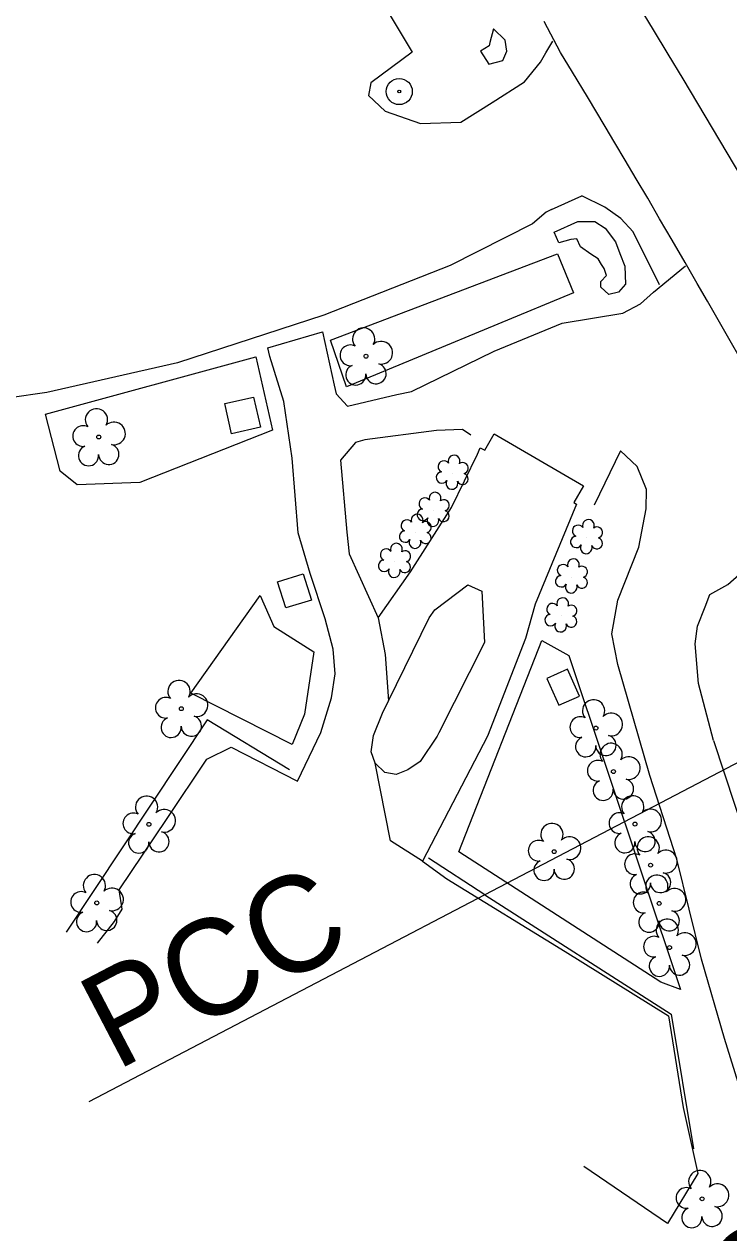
# Model space of a CAD drawing. Extents: x 471894 to 476235, y 503501 to 507878.
# Drawn here: x 474140.1 to 474257.8, y 505265.7 to 505467.5 of the extents above; entities that cross this region are included whole.
import ezdxf

# ---------------------------------------------------------------- set-up
doc = ezdxf.new("R2010")
doc.units = 0
for name, color, linetype in [('Exist Horizontal Alignment', 7, 'Continuous'), ('Exist Other Culture Area Outline', 7, 'Continuous'), ('Exist Other Culture Fence Line', 7, 'Continuous'), ('Exist Other Culture Sign Post CELL', 7, 'Continuous'), ('Exist Roads EOP', 7, 'Continuous'), ('Exist Roads EOP Other', 7, 'Continuous'), ('Exist Roads Soil', 7, 'Continuous'), ('Exist Vegetation Hedge Row', 7, 'Continuous'), ('Exist Vegetation Shrub CELL', 7, 'Continuous'), ('Exist Vegetation Tree CELL', 7, 'Continuous')]:
    doc.layers.add(name, color=color, linetype=linetype)

msp = doc.modelspace()

# ---------------------------------------------------------------- linework, layer by layer
at = {"layer": 'Exist Horizontal Alignment'}
msp.add_line((474298.4, 505364.65), (474150.86, 505287.54), dxfattribs=at)
msp.add_arc((472721.75, 504540.63), 1782.75, 27.59346, 37.45515, dxfattribs=at)
at = {"layer": 'Exist Other Culture Area Outline'}
for points in [[(474216.27, 505463), (474217.67, 505460.82), (474220.04, 505461.45), (474220.7, 505463), (474220.4, 505464.83), (474218.45, 505466.71), (474217.83, 505464.46), (474217.75, 505463.87), (474216.27, 505463)], [(474228.56, 505432.79), (474232.53, 505434.56), (474235.38, 505434.56), (474237.12, 505433.42), (474238.83, 505431.14), (474239.57, 505429.24), (474240.4, 505427.1), (474240.52, 505424.12), (474239.35, 505422.76), (474237.74, 505422.35), (474236.36, 505423.61), (474236.37, 505424.55), (474237.33, 505425.54), (474236.94, 505426.72), (474236.52, 505427.4), (474235.92, 505428.3), (474234.73, 505429.09), (474232.99, 505430.32), (474232.36, 505431.66), (474231.37, 505431.58), (474229.36, 505431.02), (474228.56, 505432.79)], [(474216.99, 505396.36), (474218.58, 505399.1), (474233.47, 505390.41), (474231.87, 505387.65)], [(474199.17, 505368.39), (474204.6, 505376.03), (474211.43, 505386.79), (474215.76, 505395.72), (474216.23, 505396.79), (474216.99, 505396.36)], [(474231.87, 505387.65), (474232.33, 505387.38), (474225.44, 505370.68), (474223.79, 505364.95), (474217.45, 505348.64), (474206.6, 505327.72)], [(474200.9, 505354.51), (474207.69, 505368.38), (474208.66, 505369.71), (474214.15, 505373.88), (474216.49, 505372.84), (474216.94, 505364.28), (474209.34, 505349.17), (474209.04, 505348.59)], [(474209.04, 505348.59), (474206.23, 505344.39), (474204.14, 505342.99), (474202.21, 505342.23), (474200.3, 505342.54), (474198.68, 505344.13)]]:
    msp.add_lwpolyline(points, dxfattribs=at)
for points in [[(474178.37, 505405.24), (474179.52, 505400.2), (474174.71, 505399.09), (474173.56, 505404.14)], [(474186.69, 505375.73), (474188.04, 505371.34), (474183.75, 505370.02), (474182.4, 505374.41)], [(474232.8, 505355.3), (474230.84, 505359.79), (474227.38, 505358.27), (474229.34, 505353.79)]]:
    msp.add_lwpolyline(points, close=True, dxfattribs=at)
at = {"layer": 'Exist Other Culture Fence Line'}
msp.add_line((474216.98, 505322.12), (474207.6, 505328.23), dxfattribs=at)
for points in [[(474184.41, 505342.98), (474170.61, 505351.37), (474147.1, 505315.91)], [(474216.98, 505322.12), (474248.11, 505302.17), (474251.85, 505279.72)]]:
    msp.add_lwpolyline(points, dxfattribs=at)
at = {"layer": 'Exist Other Culture Sign Post CELL'}
for radius in [2.18, 0.24]:
    msp.add_circle((474202.71, 505456.26), radius, dxfattribs=at)
at = {"layer": 'Exist Roads EOP'}
msp.add_lwpolyline([(474260.13, 505410.87), (474257.52, 505415.42), (474255.54, 505418.91), (474254.18, 505421.27), (474252.48, 505424.21), (474250.45, 505427.73), (474248.28, 505431.45), (474246.2, 505435.02), (474244.21, 505438.44), (474242.29, 505441.7), (474240.47, 505444.8), (474238.74, 505447.71), (474237.11, 505450.45), (474234.14, 505455.37), (474231.63, 505459.51), (474229.65, 505462.8), (474226.94, 505467.93)], dxfattribs=at)
at = {"layer": 'Exist Roads EOP Other'}
for points in [[(474240.08, 505419.23), (474243.02, 505420.83), (474245.17, 505422.77), (474250.5, 505427.16)], [(474204.78, 505406.18), (474218.56, 505412.89), (474229.93, 505417.6), (474240.08, 505419.23)], [(474152.34, 505314.06), (474155.13, 505317.69), (474156.41, 505319.75), (474155.95, 505322.96), (474163.93, 505334.88), (474170.58, 505344.75), (474174.66, 505346.79), (474185.7, 505341.11), (474189.6, 505349.23), (474191.38, 505354.99), (474192.02, 505359.03), (474191.66, 505363.17), (474190.36, 505368.21), (474187.83, 505375.77), (474185.84, 505382.55), (474184.83, 505395.03), (474183.41, 505404.52), (474181.11, 505412.03), (474180.76, 505413.48), (474189.87, 505416.13), (474191.84, 505407.24), (474192.2, 505405.79)], [(474192.2, 505405.79), (474194.08, 505403.72), (474202.33, 505405.69), (474204.78, 505406.18)], [(474214.68, 505398.88), (474213.3, 505399.84), (474208.95, 505399.65), (474196.99, 505398.12), (474195.42, 505397.64), (474192.88, 505394.69)], [(474192.88, 505394.69), (474193.94, 505382.68), (474194.36, 505379.06), (474199.17, 505368.39)], [(474239.69, 505396.26), (474235.25, 505387.21)], [(474244.58, 505342.07), (474239.22, 505360.6), (474238.2, 505365.68), (474239.2, 505371.3), (474242.71, 505380.18), (474243.98, 505386.58), (474244.01, 505389.79), (474242.43, 505393.65), (474239.69, 505396.26)], [(474255.2, 505347.88), (474252.68, 505357.39), (474252.15, 505364.02), (474252.53, 505366.97), (474253.79, 505370.24), (474254.59, 505372.28), (474257.6, 505373.92), (474262.76, 505378.5)], [(474199.17, 505368.39), (474200.35, 505362.25), (474200.9, 505354.51)], [(474198.68, 505344.13), (474198.05, 505346), (474198.39, 505348.73), (474199.9, 505352.45), (474200.9, 505354.51)], [(474255.2, 505347.88), (474262.34, 505326.27), (474268.91, 505307.01), (474272.6, 505297.55), (474282.7, 505281.77), (474287.12, 505273.12), (474286.07, 505270.82), (474285.47, 505267.68), (474285.75, 505264.57), (474287.25, 505261.46), (474289.99, 505259.33), (474310.71, 505247.24), (474328.8, 505234.96), (474323.9, 505226.78), (474305.98, 505237.39), (474292.34, 505242.83), (474281.37, 505243.82)], [(474206.6, 505327.72), (474201.23, 505331.13), (474198.68, 505344.13)], [(474261.34, 505272.77), (474261.44, 505272.96), (474262.1, 505279.36), (474259.8, 505289.16), (474257.04, 505298.11), (474253.18, 505311.36), (474249.07, 505328.08), (474244.58, 505342.07)], [(474206.6, 505327.72), (474210.68, 505324.77)], [(474210.68, 505324.77), (474230.41, 505312.63), (474247.71, 505301.94), (474250.15, 505286.6), (474252.56, 505275.57), (474247.5, 505267.26), (474233.55, 505276.73)]]:
    msp.add_lwpolyline(points, dxfattribs=at)
at = {"layer": 'Exist Roads Soil'}
msp.add_line((474228.12, 505436.59), (474233.23, 505438.84), dxfattribs=at)
for points in [[(474147.52, 505551.93), (474152.49, 505545.7), (474158.14, 505545.1), (474171.39, 505522.9), (474181.45, 505504.07), (474186.89, 505493.52), (474194.75, 505479.78), (474204.89, 505462.83), (474197.95, 505457.72), (474197.58, 505455.59), (474200.37, 505452.99), (474206.26, 505450.93), (474213.01, 505451.16), (474218.25, 505454.41), (474218.31, 505454.46)], [(474218.25, 505454.41), (474223.63, 505457.86), (474226.28, 505461.16), (474227.21, 505462.72), (474228.37, 505464.67)], [(474246.16, 505423.97), (474241.8, 505432.81), (474239.72, 505435.05), (474237.07, 505436.97), (474233.23, 505438.84)], [(474228.12, 505436.59), (474227.26, 505436.1), (474224.95, 505434.15), (474211.23, 505427.19), (474190.11, 505418.93), (474165.67, 505410.96), (474143.83, 505405.99), (474125.24, 505403.34), (474107.83, 505398.33), (474084.22, 505390.66), (474064.09, 505386.02), (474044.24, 505384.93), (474035.93, 505385.56), (474009.8, 505380.07), (473983.65, 505373.67), (473959.56, 505366.06), (473936.34, 505362.37), (473912.69, 505359.51), (473902.96, 505366.22)]]:
    msp.add_lwpolyline(points, dxfattribs=at)
at = {"layer": 'Exist Vegetation Hedge Row'}
for points in [[(474193.93, 505406.96), (474191.23, 505414.72), (474229.12, 505429.18), (474231.8, 505422.64), (474193.93, 505406.96)], [(474143.62, 505402.36), (474178.76, 505411.97), (474181.55, 505399.7), (474159.41, 505390.98), (474148.91, 505390.56), (474146.08, 505392.84), (474143.62, 505402.36)], [(474184.85, 505347.22), (474167.92, 505355.77), (474179.48, 505372.12), (474181.78, 505366.95), (474188.43, 505362.69), (474186.88, 505352.31), (474184.85, 505347.22)], [(474246.42, 505307.51), (474212.68, 505329.28), (474226.55, 505364.59), (474231.04, 505362.11), (474249.66, 505306.33), (474246.42, 505307.51)]]:
    msp.add_lwpolyline(points, dxfattribs=at)
at = {"layer": 'Exist Vegetation Shrub CELL'}
for p, q in [((474211.64, 505392.5), (474211.64, 505392.5)), ((474208.46, 505386.31), (474208.46, 505386.31)), ((474205.48, 505382.64), (474205.48, 505382.64)), ((474234.07, 505381.75), (474234.07, 505381.75)), ((474202, 505377.79), (474202, 505377.79)), ((474231.56, 505375.19), (474231.56, 505375.19)), ((474229.79, 505368.69), (474229.79, 505368.69))]:
    msp.add_line(p, q, dxfattribs=at)
for centre, radius, start, end in [((474210.16, 505393.63), 0.968, 35.8908, 245.4216), ((474211.87, 505394.54), 0.99, 334.8391, 200.4717), ((474209.84, 505391.8), 0.955, 95.1099, 327.9534), ((474213.28, 505391.57), 0.937, 204.9913, 73.4601), ((474213.31, 505393.37), 0.929, 284.4567, 126.0861), ((474211.51, 505390.82), 0.984, 151.2797, 21.387), ((474206.98, 505387.43), 0.968, 35.8908, 245.4216), ((474208.69, 505388.35), 0.99, 334.8391, 200.4717), ((474206.66, 505385.6), 0.955, 95.1099, 327.9534), ((474210.13, 505387.17), 0.929, 284.4567, 126.0861), ((474203.99, 505383.77), 0.968, 35.8908, 245.4216), ((474205.7, 505384.68), 0.99, 334.8391, 200.4717), ((474207.15, 505383.51), 0.929, 284.4567, 126.0861), ((474208.33, 505384.62), 0.984, 151.2797, 21.387), ((474210.1, 505385.38), 0.937, 204.9913, 73.4601), ((474234.3, 505383.79), 0.99, 334.8391, 200.4717), ((474203.68, 505381.94), 0.955, 95.1099, 327.9534), ((474207.11, 505381.71), 0.937, 204.9913, 73.4601), ((474232.59, 505382.88), 0.968, 35.8908, 245.4216), ((474235.74, 505382.62), 0.929, 284.4567, 126.0861), ((474202.23, 505379.83), 0.99, 334.8391, 200.4717), ((474205.35, 505380.96), 0.984, 151.2797, 21.387), ((474232.27, 505381.05), 0.955, 95.1099, 327.9534), ((474233.94, 505380.07), 0.984, 151.2797, 21.387), ((474235.71, 505380.82), 0.937, 204.9913, 73.4601), ((474200.52, 505378.91), 0.968, 35.8908, 245.4216), ((474203.68, 505378.65), 0.929, 284.4567, 126.0861), ((474200.2, 505377.08), 0.955, 95.1099, 327.9534), ((474201.87, 505376.1), 0.984, 151.2797, 21.387), ((474203.64, 505376.86), 0.937, 204.9913, 73.4601), ((474230.08, 505376.31), 0.968, 35.8908, 245.4216), ((474231.79, 505377.23), 0.99, 334.8391, 200.4717), ((474233.23, 505376.06), 0.929, 284.4567, 126.0861), ((474229.76, 505374.48), 0.955, 95.1099, 327.9534), ((474233.2, 505374.26), 0.937, 204.9913, 73.4601), ((474231.43, 505373.5), 0.984, 151.2797, 21.387), ((474228.31, 505369.82), 0.968, 35.8908, 245.4216), ((474230.02, 505370.73), 0.99, 334.8391, 200.4717), ((474231.46, 505369.56), 0.929, 284.4567, 126.0861), ((474227.99, 505367.99), 0.955, 95.1099, 327.9534), ((474231.43, 505367.76), 0.937, 204.9913, 73.4601), ((474229.66, 505367.01), 0.984, 151.2797, 21.387)]:
    msp.add_arc(centre, radius, start, end, dxfattribs=at)
at = {"layer": 'Exist Vegetation Tree CELL'}
for p, q in [((474197.16, 505412.06), (474197.16, 505412.06)), ((474152.52, 505398.58), (474152.52, 505398.58)), ((474166.31, 505353.2), (474166.31, 505353.2)), ((474235.56, 505349.97), (474235.56, 505349.97)), ((474238.49, 505342.7), (474238.49, 505342.7)), ((474242.09, 505333.94), (474242.09, 505333.94)), ((474160.9, 505333.89), (474160.9, 505333.89)), ((474228.59, 505329.33), (474228.59, 505329.33)), ((474244.69, 505327.07), (474244.69, 505327.07)), ((474152.19, 505320.77), (474152.19, 505320.77)), ((474246.13, 505320.69), (474246.13, 505320.69)), ((474247.86, 505313.31), (474247.86, 505313.31)), ((474253.3, 505271.35), (474253.3, 505271.35))]:
    msp.add_line(p, q, dxfattribs=at)
for centre in [(474197.16, 505412.06), (474152.52, 505398.58), (474166.31, 505353.2), (474235.56, 505349.97), (474238.49, 505342.7), (474160.9, 505333.89), (474242.09, 505333.94), (474228.59, 505329.33), (474244.69, 505327.07), (474152.19, 505320.77), (474246.13, 505320.69), (474247.86, 505313.31), (474253.3, 505271.35)]:
    msp.add_circle(centre, 0.326, dxfattribs=at)
for centre, radius, start, end in [((474196.77, 505414.93), 1.86, 330.1651, 219.7134), ((474194.55, 505412.21), 1.73, 62.6636, 279.3457), ((474199.71, 505412.65), 1.9, 257.1011, 134.1999), ((474198.83, 505409.16), 1.7, 181.2822, 74.56), ((474195.45, 505408.94), 1.69, 111.5671, 6.231), ((474152.14, 505401.45), 1.86, 330.1651, 219.7134), ((474155.07, 505399.17), 1.9, 257.1011, 134.1999), ((474149.92, 505398.73), 1.73, 62.6636, 279.3457), ((474150.82, 505395.46), 1.69, 111.5671, 6.231), ((474154.2, 505395.68), 1.7, 181.2822, 74.56), ((474165.93, 505356.08), 1.86, 330.1651, 219.7134), ((474163.71, 505353.36), 1.73, 62.6636, 279.3457), ((474168.86, 505353.79), 1.9, 257.1011, 134.1999), ((474235.17, 505352.84), 1.86, 330.1651, 219.7134), ((474238.1, 505350.56), 1.9, 257.1011, 134.1999), ((474164.61, 505350.08), 1.69, 111.5671, 6.231), ((474167.99, 505350.3), 1.7, 181.2822, 74.56), ((474232.95, 505350.12), 1.73, 62.6636, 279.3457), ((474233.85, 505346.85), 1.69, 111.5671, 6.231), ((474237.23, 505347.07), 1.7, 181.2822, 74.56), ((474238.1, 505345.57), 1.86, 330.1651, 219.7134), ((474235.88, 505342.85), 1.73, 62.6636, 279.3457), ((474241.04, 505343.29), 1.9, 257.1011, 134.1999), ((474236.78, 505339.58), 1.69, 111.5671, 6.231), ((474240.16, 505339.8), 1.7, 181.2822, 74.56), ((474160.52, 505336.76), 1.86, 330.1651, 219.7134), ((474241.71, 505336.82), 1.86, 330.1651, 219.7134), ((474163.45, 505334.48), 1.9, 257.1011, 134.1999), ((474244.64, 505334.53), 1.9, 257.1011, 134.1999), ((474158.3, 505334.04), 1.73, 62.6636, 279.3457), ((474228.21, 505332.2), 1.86, 330.1651, 219.7134), ((474239.49, 505334.1), 1.73, 62.6636, 279.3457), ((474159.2, 505330.77), 1.69, 111.5671, 6.231), ((474162.58, 505330.99), 1.7, 181.2822, 74.56), ((474240.39, 505330.82), 1.69, 111.5671, 6.231), ((474243.76, 505331.04), 1.7, 181.2822, 74.56), ((474225.99, 505329.49), 1.73, 62.6636, 279.3457), ((474231.14, 505329.92), 1.9, 257.1011, 134.1999), ((474244.3, 505329.95), 1.86, 330.1651, 219.7134), ((474230.27, 505326.43), 1.7, 181.2822, 74.56), ((474242.08, 505327.23), 1.73, 62.6636, 279.3457), ((474247.23, 505327.66), 1.9, 257.1011, 134.1999), ((474226.89, 505326.21), 1.69, 111.5671, 6.231), ((474151.8, 505323.65), 1.86, 330.1651, 219.7134), ((474242.98, 505323.95), 1.69, 111.5671, 6.231), ((474245.74, 505323.56), 1.86, 330.1651, 219.7134), ((474246.36, 505324.18), 1.7, 181.2822, 74.56), ((474149.58, 505320.93), 1.73, 62.6636, 279.3457), ((474154.74, 505321.36), 1.9, 257.1011, 134.1999), ((474243.52, 505320.84), 1.73, 62.6636, 279.3457), ((474248.68, 505321.28), 1.9, 257.1011, 134.1999), ((474150.49, 505317.65), 1.69, 111.5671, 6.231), ((474153.86, 505317.87), 1.7, 181.2822, 74.56), ((474244.42, 505317.57), 1.69, 111.5671, 6.231), ((474247.48, 505316.19), 1.86, 330.1651, 219.7134), ((474247.8, 505317.79), 1.7, 181.2822, 74.56), ((474250.41, 505313.9), 1.9, 257.1011, 134.1999), ((474245.26, 505313.47), 1.73, 62.6636, 279.3457), ((474246.16, 505310.19), 1.69, 111.5671, 6.231), ((474249.53, 505310.41), 1.7, 181.2822, 74.56), ((474252.91, 505274.23), 1.86, 330.1651, 219.7134), ((474255.85, 505271.94), 1.9, 257.1011, 134.1999), ((474250.69, 505271.51), 1.73, 62.6636, 279.3457), ((474251.59, 505268.23), 1.69, 111.5671, 6.231), ((474254.97, 505268.45), 1.7, 181.2822, 74.56)]:
    msp.add_arc(centre, radius, start, end, dxfattribs=at)

# ---------------------------------------------------------------- texts
at = {"layer": 'Exist Horizontal Alignment'}
for rotation, p in [(27.5935, (474155.41, 505292.63)), (26.3631, (474232.52, 505234.87))]:
    msp.add_text('PCC', height=16, rotation=rotation, dxfattribs=at).set_placement(p)

doc.saveas('drawing.dxf')
